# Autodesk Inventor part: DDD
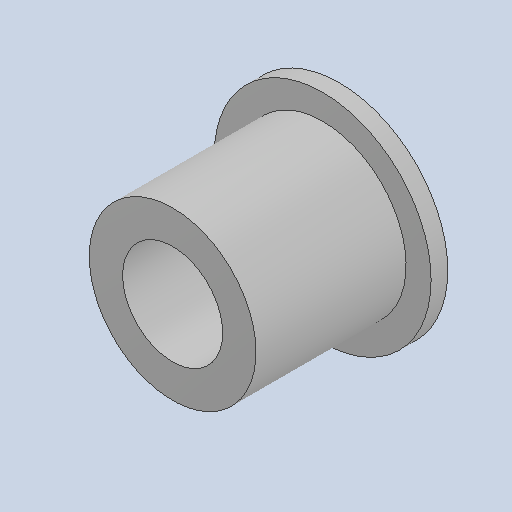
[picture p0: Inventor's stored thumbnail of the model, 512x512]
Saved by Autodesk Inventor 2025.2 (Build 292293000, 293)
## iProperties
Created: 2025-04
Part Number: DDD
Material: Generic
Description: NOT SPECIFIED
Document SubType Name: Modeling
Designer: BennF
Density: 1 g/cm^3
Appearance: Default
Author: BennF
Revision Number: 2LAST_VERSION
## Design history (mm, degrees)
feature "Base1"
body "Solid1"
